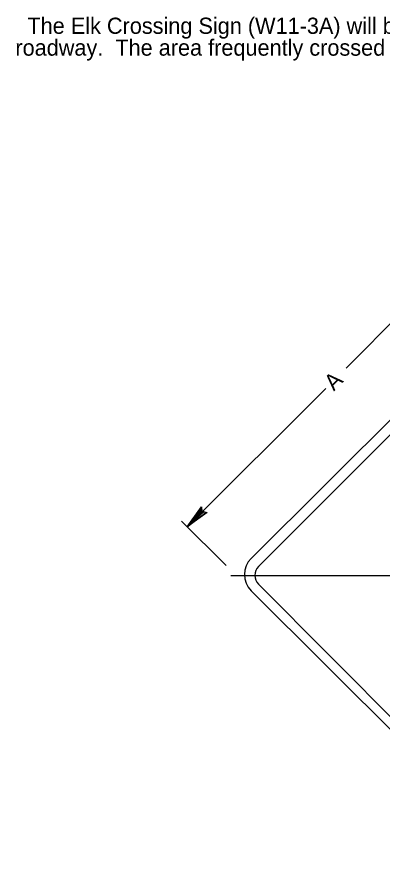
# Model space of a CAD drawing. Extents: x 0.013 to 0.196, y 0.005 to 0.259.
# Drawn here: x 0.0293 to 0.0857, y 0.1074 to 0.237 of the extents above; entities that cross this region are included whole.
import ezdxf

# ---------------------------------------------------------------- set-up
doc = ezdxf.new("R2010")
doc.units = 0
for name, color, linetype in [('11', 7, 'Continuous'), ('2', 7, 'Continuous'), ('3', 7, 'Continuous')]:
    doc.layers.add(name, color=color, linetype=linetype)

# ---------------------------------------------------------------- blocks, each defined once
blk = doc.blocks.new('RARROW')
at = {"layer": '3'}
for p, q in [((-2.156, 0.28500000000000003), (-2.2665, 0.384625)), ((-2.2665, 0.384625), (0, 0)), ((0, 0), (-2.2665, -0.379125)), ((-2.156, 0.28500000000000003), (-2.075625, 0.12075)), ((0, 0), (-2.156, 0.28500000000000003)), ((-2.14975, -0.2705), (0, 0)), ((-2.075625, 0.12075), (0, 0)), ((0, 0), (-2.074, -0.108)), ((-2.2665, -0.379125), (-2.14975, -0.2705)), ((-2.074, -0.108), (-2.14975, -0.2705))]:
    blk.add_line(p, q, dxfattribs=at)

msp = doc.modelspace()

# ---------------------------------------------------------------- linework, layer by layer
at = {"layer": '11'}
for p, q in [((0.0655, 0.153375), (0.1065, 0.19425)), ((0.1065, 0.107375), (0.0655, 0.148375))]:
    msp.add_line(p, q, dxfattribs=at)
msp.add_arc((0.06803372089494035, 0.15087500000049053), 0.0035594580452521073, 135.38381666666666, 224.61618055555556, dxfattribs=at)
at = {"layer": '3'}
for p, q in [((0.080125, 0.18275), (0.1015, 0.20425000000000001)), ((0.066625, 0.152125), (0.1075, 0.193125)), ((0.077, 0.179625), (0.055625, 0.15825)), ((0.061625, 0.15225), (0.05475, 0.15912500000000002)), ((0.062375, 0.15075), (0.1545, 0.15075)), ((0.1075, 0.10825), (0.066625, 0.149375))]:
    msp.add_line(p, q, dxfattribs=at)
msp.add_arc((0.06801854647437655, 0.1507499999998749), 0.0019577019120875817, 135.38381944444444, 224.61618333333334, dxfattribs=at)

# ---------------------------------------------------------------- block references
at = {"layer": '3', "xscale": 0.0016545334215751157, "yscale": 0.001636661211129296, "rotation": -135}
msp.add_blockref('RARROW', (0.055625, 0.15825), dxfattribs=at)

# ---------------------------------------------------------------- texts
at = {"layer": '2'}
for s, p in [('  The Elk Crossing Sign (W11-3A) will be authorized to warn of the unexpected hazard of elk crossing the', (0.029125, 0.234375)), ('roadway.  The area frequently crossed by elk will be designated by the Game Commission.', (0.029125, 0.231))]:
    msp.add_text(s, height=0.0024997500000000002, dxfattribs=at).set_placement(p)
at = {"layer": '3'}
msp.add_text('A', height=0.0024997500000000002, rotation=45, dxfattribs=at).set_placement((0.07825, 0.179125))

doc.saveas('drawing.dxf')
